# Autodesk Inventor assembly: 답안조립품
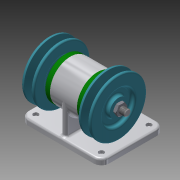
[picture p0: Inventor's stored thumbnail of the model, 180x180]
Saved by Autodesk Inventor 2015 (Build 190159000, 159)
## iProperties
Created: 2019-09
Part Number: 답안조립품
Document SubType Name: Assembly
Designer: now
Author: now
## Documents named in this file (10)
- C:\Users\now\Desktop\490904V1036\답안조립품.iam
- C:\Users\now\Desktop\490904V1036\V-벨트풀리.ipt
- C:\Users\now\Desktop\490904V1036\너트 M10x1.ipt
- C:\Users\now\Desktop\490904V1036\베어링 6004.ipt
- C:\Users\now\Desktop\490904V1036\본체.ipt
- C:\Users\now\Desktop\490904V1036\볼트 M4.ipt
- C:\Users\now\Desktop\490904V1036\오일 실 17 30 5.ipt
- C:\Users\now\Desktop\490904V1036\축.ipt
- C:\Users\now\Desktop\490904V1036\커버.ipt
- C:\Users\now\Desktop\490904V1036\키 5 x 5 x 12.ipt
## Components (2 placed, 1 different names)
1. V-벨트풀리:1 — 각도:3
2. V-벨트풀리:2 — 각도:4
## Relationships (2: Angle 2)
- 각도:3 [Angle]: V-벨트풀리:1
- 각도:4 [Angle]: V-벨트풀리:2
